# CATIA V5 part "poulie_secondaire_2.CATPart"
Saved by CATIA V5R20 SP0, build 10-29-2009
Part number: poulie_secondaire_2
Bounding box of the stored display mesh (mm): x 625.778 to 705.778, y -870.981 to -431.333, z -872.09 to -432.092
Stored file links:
  C:\Users\Mike-7\Desktop\MMS_GR3\bfoltzer\CFAO_bfoltzer\poulie_secondaire_2.CATPart
  D:\ecole\thinkmotion\Eolienne.CATProduct
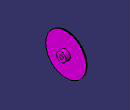
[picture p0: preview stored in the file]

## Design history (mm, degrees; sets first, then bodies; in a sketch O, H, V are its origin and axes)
Set1
  Plane1: linked copy from another document
  Point1 to Point6: linked copy from another document
  Line1: linked copy from another document
  Point7: linked copy from another document
  Point8: linked copy from another document
Body1 (main body)
  Sketch1 on Plane1, origin (0, -6491.4671, 9516.4892), H (-1, 0, 0), V (0, 0.498, -0.8672)
    point P1 (-625.7782, 11691.4334)
    line L1 (-625.7782, 11691.4334) -> (-645.7782, 11691.4334)
    line L2 (-645.7782, 11691.4334) -> (-645.7782, 11671.4334)
    line L3 (-645.7782, 11671.4334) -> (-625.7782, 11671.4334)
    line L4 (-625.7782, 11671.4334) -> (-625.7782, 11691.4334)
    point P3 (-645.7782, 11671.4334)
    reference projected point E1 (-645.7782, 11671.4334) from Point1
    reference projected point E2 (-625.7782, 11691.4334) from Point2
    point P5 (-655.7782, 11506.4334)
    line L5 (-655.7782, 11506.4334) -> (-645.7782, 11506.4334)
    line L6 (-645.7782, 11506.4334) -> (-645.7782, 11706.4334)
    line L7 (-645.7782, 11706.4334) -> (-655.7782, 11706.4334)
    line L8 (-655.7782, 11706.4334) -> (-655.7782, 11506.4334)
    point P7 (-645.7782, 11706.4334)
    point P8 (-655.7782, 11706.4334)
    reference projected point E3 (-655.7782, 11506.4334) from Point3
    reference projected point E4 (-645.7782, 11706.4334) from Point4
    point P9 (-705.7782, 11676.4334)
    line L9 (-705.7782, 11676.4334) -> (-655.7782, 11676.4334)
    line L10 (-655.7782, 11676.4334) -> (-655.7782, 11706.4334)
    line L11 (-655.7782, 11706.4334) -> (-705.7782, 11706.4334)
    line L12 (-705.7782, 11706.4334) -> (-705.7782, 11676.4334)
    point P11 (-655.7782, 11706.4334)
    reference projected point E5 (-705.7782, 11676.4334) from Point5
    reference projected point E6 (-655.7782, 11706.4334) from Point6
    horizontal: L1 H, L3 H, L5 H, L7 H, L9 H, L11 H
    vertical: L2 V, L4 V, L6 V, L8 V, L10 V, L12 V
    coincidence: P3 E1, P1 E2, E3 P5, P7 E4, P9 E5, P11 E6, P8 P11
  Shaft1: profile Sketch1, axis Line1, angle 360
  Sketch2 on Plane1, origin (0, -6491.4671, 9516.4892), H (-1, 0, 0), V (0, 0.498, -0.8672)
    point P1 (-649.2782, 11507.4334)
    line L1 (-649.2782, 11507.4334) -> (-652.2782, 11507.4334)
    line L2 (-652.2782, 11507.4334) -> (-652.2782, 11506.4334)
    line L3 (-652.2782, 11506.4334) -> (-649.2782, 11506.4334)
    line L4 (-649.2782, 11506.4334) -> (-649.2782, 11507.4334)
    point P3 (-652.2782, 11506.4334)
    reference projected point E1 (-649.2782, 11507.4334) from Point7
    reference projected point E2 (-652.2782, 11506.4334) from Point8
    horizontal: L1 H, L3 H
    vertical: L2 V, L4 V
    coincidence: P1 E1, P3 E2
  Groove1: profile Sketch2, axis Line1, angle 360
